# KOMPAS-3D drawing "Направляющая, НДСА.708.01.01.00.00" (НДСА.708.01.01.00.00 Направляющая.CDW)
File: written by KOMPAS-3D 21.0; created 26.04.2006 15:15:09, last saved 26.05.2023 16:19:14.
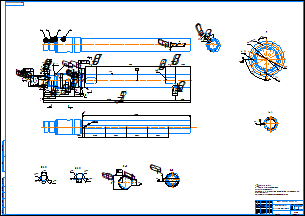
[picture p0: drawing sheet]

Sheet 1: A0, landscape

Document properties: Полное имя файла: C:\Users\s.pischagina\Desktop\PLM\НДСА.708.01.01.00.00 Направляющая.CDW; Автор: Устинов А.В.; Организация: ЭСТО-Вакуум; 245497770678: <item xmlns="http://appius.ru/pdm" xmlns:xs="http://www.w3.org/2001/XMLSchema" xmlns:xsi="http://www.w3.org/2001/XMLSchema-instance" xsi:type="item">  <element xmlns:d2p1="http://v8.1c.ru/8.1/data/enterprise/current-config" xsi:type="d2p1:CatalogRef.aps_Элемен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; PLM_CDWXDTO: <item xmlns="http://appius.ru/pdm" xmlns:xs="http://www.w3.org/2001/XMLSchema" xmlns:xsi="http://www.w3.org/2001/XMLSchema-instance" xsi:type="item">  <element xmlns:d2p1="http://v8.1c.ru/8.1/data/enterprise/current-config" xsi:type="d2p1:CatalogRef.aps_Элемен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; Масса: 36.462462; 247496016287: <item xmlns="http://appius.ru/pdm" xmlns:xs="http://www.w3.org/2001/XMLSchema" xmlns:xsi="http://www.w3.org/2001/XMLSchema-instance" xsi:type="item">  <element xmlns:d2p1="http://v8.1c.ru/8.1/data/enterprise/current-config" xsi:type="d2p1:CatalogRef.aps_Элемен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; 247496016387: <item xmlns="http://appius.ru/pdm" xmlns:xs="http://www.w3.org/2001/XMLSchema" xmlns:xsi="http://www.w3.org/2001/XMLSchema-instance" xsi:type="item">  <element xmlns:d2p1="http://v8.1c.ru/8.1/data/enterprise/current-config" xsi:type="d2p1:CatalogRef.aps_Элемен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; 247496016487: <item xmlns="http://appius.ru/pdm" xmlns:xs="http://www.w3.org/2001/XMLSchema" xmlns:xsi="http://www.w3.org/2001/XMLSchema-instance" xsi:type="item">  <element xmlns:d2p1="http://v8.1c.ru/8.1/data/enterprise/current-config" xsi:type="d2p1:CatalogRef.aps_Элемен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; PDM_DOCXDTO: <item xmlns="http://appius.ru/pdm" xmlns:xs="http://www.w3.org/2001/XMLSchema" xmlns:xsi="http://www.w3.org/2001/XMLSchema-instance" xsi:type="item">  <element xmlns:d2p1="http://v8.1c.ru/8.1/data/enterprise/current-config" xsi:type="d2p1:CatalogRef.aps_Элемен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; PDM_ITEMXDTO: <item xmlns="http://appius.ru/pdm" xmlns:xs="http://www.w3.org/2001/XMLSchema" xmlns:xsi="http://www.w3.org/2001/XMLSchema-instance" xsi:type="item">  <element xmlns:d2p1="http://v8.1c.ru/8.1/data/enterprise/current-config" xsi:type="d2p1:CatalogRef.aps_Элемен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; PDM_DRAWINGXDTO: <item xmlns="http://appius.ru/pdm" xmlns:xs="http://www.w3.org/2001/XMLSchema" xmlns:xsi="http://www.w3.org/2001/XMLSchema-instance" xsi:type="item">  <element xmlns:d2p1="http://v8.1c.ru/8.1/data/enterprise/current-config" xsi:type="d2p1:CatalogRef.aps_Элемен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

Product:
- Part/product: Направляющая  | designation НДСА.708.01.01.00.00
    Масса: 36.462462
    Форматы листов документа: A0
    additional columns: <item xmlns="http://appius.ru/pdm" xmlns:xs="http://www.w3.org/2001/XMLSchema" x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; <item xmlns="http://appius.ru/pdm" xmlns:xs="http://www.w3.org/2001/XMLSchema" x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; <item xmlns="http://appius.ru/pdm" xmlns:xs="http://www.w3.org/2001/XMLSchema" x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; <item xmlns="http://appius.ru/pdm" xmlns:xs="http://www.w3.org/2001/XMLSchema" x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; <item xmlns="http://appius.ru/pdm" xmlns:xs="http://www.w3.org/2001/XMLSchema" x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; <item xmlns="http://appius.ru/pdm" xmlns:xs="http://www.w3.org/2001/XMLSchema" x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
  - Component [detail]: Втулка  | designation НДСА.014.01.08.04.03  | pos. 1  | Материал: Сталь 20 ГОСТ 1050-88 (density 7859 kg/m3); Масса: 0.959708; Форматы листов документа: A4; additional columns: <item xmlns="http://appius.ru/pdm" xmlns:xs="http://www.w3.org/2001/XMLSchema" x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; <item xmlns="http://appius.ru/pdm" xmlns:xs="http://www.w3.org/2001/XMLSchema" x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; <item xmlns="http://appius.ru/pdm" xmlns:xs="http://www.w3.org/2001/XMLSchema" x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; <item xmlns="http://appius.ru/pdm" xmlns:xs="http://www.w3.org/2001/XMLSchema" x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; <item xmlns="http://appius.ru/pdm" xmlns:xs="http://www.w3.org/2001/XMLSchema" x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; <item xmlns="http://appius.ru/pdm" xmlns:xs="http://www.w3.org/2001/XMLSchema" x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; source file: НДСА.014.01.08.04.03 Втулка.CDW, НДСА.014.01.08.04.03 Втулка.m3d
  - Component [detail]: Втулка  | designation НДСА.014.01.08.04.01  | pos. 2  | Материал: Сталь 20 ГОСТ 1050-88 (density 7859 kg/m3); Масса: 1.411167; Форматы листов документа: A4; additional columns: <item xmlns="http://appius.ru/pdm" xmlns:xs="http://www.w3.org/2001/XMLSchema" x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; <item xmlns="http://appius.ru/pdm" xmlns:xs="http://www.w3.org/2001/XMLSchema" x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; <item xmlns="http://appius.ru/pdm" xmlns:xs="http://www.w3.org/2001/XMLSchema" x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; <item xmlns="http://appius.ru/pdm" xmlns:xs="http://www.w3.org/2001/XMLSchema" x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; <item xmlns="http://appius.ru/pdm" xmlns:xs="http://www.w3.org/2001/XMLSchema" x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; <item xmlns="http://appius.ru/pdm" xmlns:xs="http://www.w3.org/2001/XMLSchema" x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; source file: НДСА.014.01.08.04.01 Втулка.CDW, НДСА.014.01.08.04.01 Втулка.m3d
  - Component [detail]: Труба  | designation НДСА.014.01.08.04.02  | pos. 3  | Материал: Труба$d114х8 ГОСТ 8732-78;20 ГОСТ 8731-74$ (density 7859 kg/m3); Масса: 1.170395; Форматы листов документа: A4; additional columns: <item xmlns="http://appius.ru/pdm" xmlns:xs="http://www.w3.org/2001/XMLSchema" x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; <item xmlns="http://appius.ru/pdm" xmlns:xs="http://www.w3.org/2001/XMLSchema" x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; <item xmlns="http://appius.ru/pdm" xmlns:xs="http://www.w3.org/2001/XMLSchema" x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; <item xmlns="http://appius.ru/pdm" xmlns:xs="http://www.w3.org/2001/XMLSchema" x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; <item xmlns="http://appius.ru/pdm" xmlns:xs="http://www.w3.org/2001/XMLSchema" x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; <item xmlns="http://appius.ru/pdm" xmlns:xs="http://www.w3.org/2001/XMLSchema" x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; source file: НДСА.014.01.08.04.02 Труба.CDW, НДСА.014.01.08.04.02 Труба.m3d
  - Component [detail]: Труба  | designation НДСА.014.01.08.04.04  | pos. 4  | Материал: Труба$d140х10 ГОСТ 8732-78;20 ГОСТ 8731-74$ (density 7859 kg/m3); Масса: 32.921192; Форматы листов документа: A4; additional columns: <item xmlns="http://appius.ru/pdm" xmlns:xs="http://www.w3.org/2001/XMLSchema" x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; <item xmlns="http://appius.ru/pdm" xmlns:xs="http://www.w3.org/2001/XMLSchema" x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; <item xmlns="http://appius.ru/pdm" xmlns:xs="http://www.w3.org/2001/XMLSchema" x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; <item xmlns="http://appius.ru/pdm" xmlns:xs="http://www.w3.org/2001/XMLSchema" x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; <item xmlns="http://appius.ru/pdm" xmlns:xs="http://www.w3.org/2001/XMLSchema" x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; <item xmlns="http://appius.ru/pdm" xmlns:xs="http://www.w3.org/2001/XMLSchema" x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; source file: НДСА.014.01.08.04.04 Труба.CDW, НДСА.014.01.08.04.04 Труба.m3d

Title block, sheet 1: Наименование: Направляющая / Сборочный чертеж; Масса: 36,46; scale: 1:2,5; Количество листов документа: 1; organisation: ЭСТО; Форматы листов документа: A0; stored path: D:\WorkPDM\Устинов А.В\8b0af0dc-f3da-4f92-ad11-61854faa3fd1\УКРД.789.01.03.10.00 СБ Направляющая.cdw; Разработал: Пищагина; Проверил: Белецкий; Утвердил: Виноградов; Разработал, date: 18.05.23

Views: Вид 11, Снизу, Проекционный вид 12, Проекционный вид 13, Местный разрез 1, Местный разрез 2, Вид по стрелке 14, Разрез Ж-Ж, Разрез З-З, Разрез 17, Выносной элемент 18, Выносной элемент 19, Проекционный вид 20, Вид по стрелке Г, Разрез А-А, Разрез Б-Б, Разрез В-В, Выносной элемент Д, Выносной элемент, Выносной элемент Е
Referenced files in C:\Users\s.pischagina\Desktop\PLM\: НДСА.014.01.08.04.00 Направляющая.a3d, НДСА.708.01.01.00.00 Направляющая.a3d, НДСА.014.01.08.04.04 Труба.m3d, НДСА.014.01.08.04.01 Втулка.m3d, НДСА.014.01.08.04.02 Труба.m3d, НДСА.014.01.08.04.03 Втулка.m3d, НДСА.014.01.08.04.03 Втулка.CDW, НДСА.014.01.08.04.01 Втулка.CDW, НДСА.014.01.08.04.02 Труба.CDW, НДСА.014.01.08.04.04 Труба.CDW
Referenced files in E:\НДСА.014.01.08.00.00 Гидроподъемник\: НДСА.014.01.08.04.03 Втулка.m3d
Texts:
  НДСА.708.01.01.00.00
  Js12
  JS12
  НДСА.014.01.08.04.03
  Втулка
  НДСА.014.01.08.04.01
  НДСА.014.01.08.04.02
  Труба
  НДСА.014.01.08.04.04
  НДСА.014.01.08.04.03 Втулка
  НДСА.014.01.08.04.01 Втулка
  НДСА.014.01.08.04.02 Труба
  НДСА.014.01.08.04.04 Труба
  НДСА.708.01.01.00.00 Направляющая
Dimensions and other numbers on the sheet: 20; 4; 3; 2; 1; 10; 6.3; 2 №1; 114; 140; 120; 118; 1442; 90; 33; 98; 13; 82; 12; 1,25; 2,5; 0,016; 66±0,3; 22±0,3; 235±0,5; 50; 138; 136; 290; 148±1; 100; 675±1; 15; 0,025; 6,3; -7Н; 2 отв.; 40; 149±0,2; 48±0,2; 1293±0,5; 134; 126; 8 отв.; 22 30'; 3,2; 30; 60; 2 паза; 0.4; 1055±0,5; 205±0,2; 5отв; 1:2,5; 36,46; 18.05.23

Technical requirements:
  * Размеры для справок.
  **Размеры обеспеч. инструментом.
  Сварка по ГОСТ 5264-80.
  Дет. поз. 1, 2, 3 допускается изготавливать одной деталью при
  соблюдении размеров.
  Покрытие - обработать консистентной смазкой.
